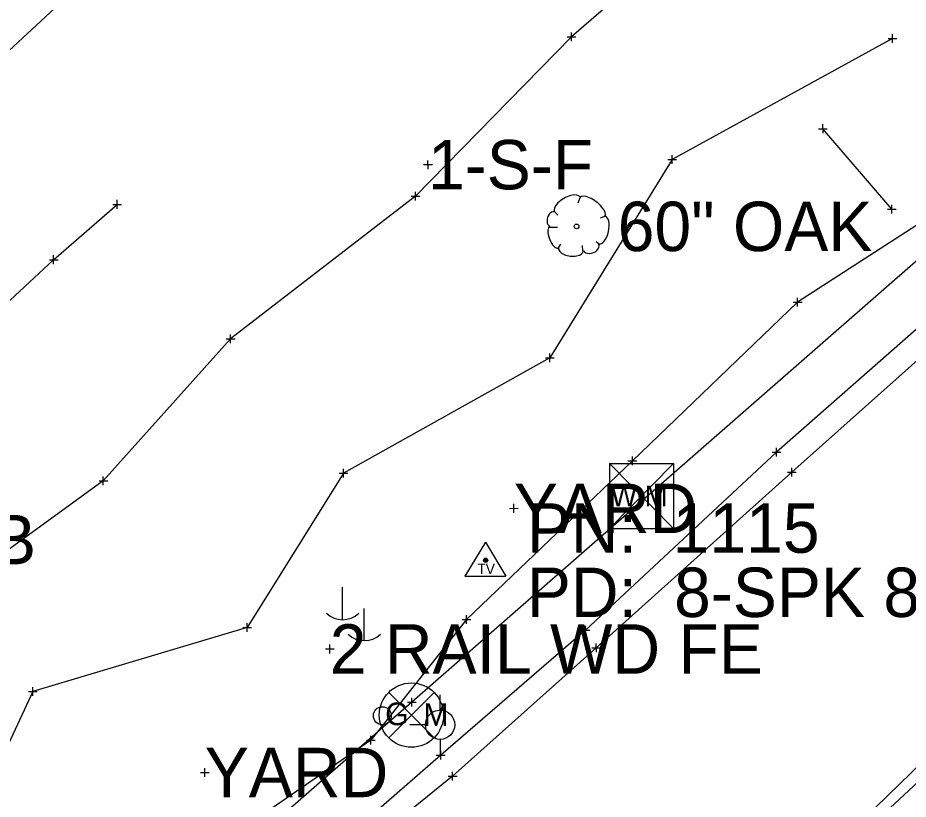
# Model space of a CAD drawing. Extents: x -1 to 1157254, y -1 to 2021979.
# Drawn here: x 1147450.2 to 1147580, y 2017460.4 to 2017574.3 of the extents above; entities that cross this region are included whole.
import ezdxf

# ---------------------------------------------------------------- set-up
doc = ezdxf.new("R2010")
doc.units = 0
for name, color, linetype in [('S_BREAKLINE', 7, 'Continuous'), ('S_BUILDING_ANNOT', 7, 'Continuous'), ('S_CAL_CORNER_ANNOT', 7, 'Continuous'), ('S_CATCH_BASIN', 7, 'Continuous'), ('S_CONTOUR_ANNOT', 7, 'Continuous'), ('S_CTL_TABLE', 7, 'Continuous'), ('S_CURB', 7, 'Continuous'), ('S_DRIVEWAY_ANNOT', 7, 'Continuous'), ('S_DTM_PAVEMENT', 7, 'Continuous'), ('S_EDGE_BITUMINOUS_ANNOT', 7, 'Continuous'), ('S_GAS_UTILITIES_ANNOT', 7, 'Continuous'), ('S_GATE', 7, 'Continuous'), ('S_GATE_ANNOT', 7, 'Continuous')]:
    doc.layers.add(name, color=color, linetype=linetype)

msp = doc.modelspace()

# ---------------------------------------------------------------- linework, layer by layer
at = {"layer": 'S_BREAKLINE'}
for p, q in [((1147518.43, 2017497.83), (1147515.42, 2017492.88)), ((1147518.43, 2017497.83), (1147521.37, 2017492.88)), ((1147515.42, 2017492.88), (1147521.37, 2017492.88))]:
    msp.add_line(p, q, dxfattribs=at)
for radius in [0.311, 0.183, 0.103]:
    msp.add_circle((1147518.43, 2017495.22), radius, dxfattribs=at)
at = {"layer": 'S_BUILDING_ANNOT'}
for p, q in [((1147566.97, 2017558.11), (1147568.24, 2017558.11)), ((1147567.61, 2017557.48), (1147567.6, 2017558.75)), ((1147567.6, 2017558.11), (1147567.6, 2017558.11)), ((1147509.39, 2017552.87), (1147510.66, 2017552.87)), ((1147510.03, 2017552.23), (1147510.02, 2017553.5)), ((1147510.03, 2017552.87), (1147510.03, 2017552.87)), ((1147577, 2017546.39), (1147578.27, 2017546.4)), ((1147577.64, 2017545.76), (1147577.64, 2017547.03)), ((1147577.64, 2017546.4), (1147577.64, 2017546.4)), ((1147560.84, 2017510.32), (1147560.83, 2017511.59)), ((1147560.2, 2017510.95), (1147561.47, 2017510.95)), ((1147560.84, 2017510.95), (1147560.84, 2017510.95)), ((1147563.07, 2017507.42), (1147563.07, 2017508.69)), ((1147562.43, 2017508.05), (1147563.7, 2017508.06)), ((1147563.07, 2017508.05), (1147563.07, 2017508.05)), ((1147522.54, 2017502.14), (1147522.54, 2017503.41)), ((1147521.9, 2017502.77), (1147523.18, 2017502.78)), ((1147522.54, 2017502.77), (1147522.54, 2017502.77)), ((1147533.01, 2017484.38), (1147533.01, 2017485.66)), ((1147532.37, 2017485.02), (1147533.64, 2017485.02)), ((1147533.01, 2017485.02), (1147533.01, 2017485.02)), ((1147495.72, 2017481.64), (1147495.71, 2017482.92)), ((1147534.57, 2017481.82), (1147534.56, 2017483.09)), ((1147495.08, 2017482.28), (1147496.35, 2017482.28)), ((1147495.71, 2017482.28), (1147495.71, 2017482.28)), ((1147533.93, 2017482.45), (1147535.2, 2017482.46)), ((1147534.56, 2017482.45), (1147534.56, 2017482.45)), ((1147507.67, 2017473.88), (1147507.67, 2017475.15)), ((1147507.04, 2017474.52), (1147508.31, 2017474.52)), ((1147507.67, 2017474.52), (1147507.67, 2017474.52)), ((1147511.88, 2017466.17), (1147511.88, 2017467.44)), ((1147511.24, 2017466.8), (1147512.52, 2017466.81)), ((1147511.88, 2017466.81), (1147511.88, 2017466.81)), ((1147477.49, 2017463.64), (1147477.49, 2017464.91)), ((1147476.85, 2017464.27), (1147478.12, 2017464.28)), ((1147477.49, 2017464.27), (1147477.49, 2017464.27)), ((1147512.98, 2017463.73), (1147514.26, 2017463.73)), ((1147513.62, 2017463.09), (1147513.62, 2017464.37)), ((1147513.62, 2017463.73), (1147513.62, 2017463.73))]:
    msp.add_line(p, q, dxfattribs=at)
at = {"layer": 'S_CAL_CORNER_ANNOT'}
for p, q in [((1147504.3, 2017469.33), (1147510.92, 2017475.94)), ((1147504.3, 2017475.94), (1147510.92, 2017469.33))]:
    msp.add_line(p, q, dxfattribs=at)
msp.add_lwpolyline([(1148176.11, 2017926.04), (1148136.14, 2017895.28), (1148103.22, 2017868.95), (1148054.86, 2017832.59), (1147994.13, 2017784.96), (1147955.31, 2017755.81), (1147823.06, 2017654.27), (1147729.59, 2017581.35), (1147643.02, 2017515.61), (1147594.54, 2017475.05), (1147501.21, 2017388.35), (1147435.29, 2017328.79), (1147395.53, 2017293.46), (1147348.75, 2017254.13), (1147258.66, 2017171.57), (1147166.99, 2017089.79), (1147151.24, 2017076.13), (1147027.41, 2016982.56), (1146975.56, 2016939.41), (1146851.18, 2016835.15), (1146821.23, 2016867.05), (1146788.36, 2016903.2)], dxfattribs=at)
msp.add_circle((1147507.61, 2017472.64), 4.68, dxfattribs=at)
at = {"layer": 'S_CATCH_BASIN'}
for p, q in [((1147497.52, 2017491.27), (1147497.52, 2017486.54)), ((1147500.69, 2017488.2), (1147500.69, 2017483.47)), ((1147511.79, 2017473.34), (1147511.79, 2017475.59)), ((1147509.7, 2017471.21), (1147507.37, 2017471.21)), ((1147511.87, 2017466.79), (1147511.87, 2017469.12))]:
    msp.add_line(p, q, dxfattribs=at)
for centre, radius in [((1147503.37, 2017472.55), 1.31), ((1147511.79, 2017471.23), 2.13)]:
    msp.add_circle(centre, radius, dxfattribs=at)
for centre in [(1147497.58, 2017489.96), (1147500.76, 2017486.9)]:
    msp.add_arc(centre, 3.41, 226.3972, 313.6028, dxfattribs=at)
at = {"layer": 'S_CONTOUR_ANNOT'}
for p, q in [((1147536.49, 2017509.31), (1147545.83, 2017509.31)), ((1147536.49, 2017509.31), (1147536.49, 2017499.82)), ((1147536.49, 2017509.31), (1147545.83, 2017499.82)), ((1147545.83, 2017509.31), (1147536.49, 2017499.82)), ((1147545.83, 2017509.31), (1147545.83, 2017499.82)), ((1147536.49, 2017499.82), (1147545.83, 2017499.82))]:
    msp.add_line(p, q, dxfattribs=at)
msp.add_lwpolyline([(1148171.01, 2018007.64), (1148133.82, 2017978.13), (1147884.86, 2017790.18), (1147810.34, 2017733.24), (1147725.21, 2017658.34), (1147638.36, 2017588.8), (1147507.67, 2017474.52), (1147125.41, 2017140.99), (1145970.62, 2016384.06)], dxfattribs=at)
at = {"layer": 'S_CTL_TABLE'}
for p, q in [((1147530.3, 2017571.5), (1147531.57, 2017571.5)), ((1147530.94, 2017570.87), (1147530.93, 2017572.14)), ((1147530.93, 2017571.5), (1147530.93, 2017571.5)), ((1147577.09, 2017571.25), (1147578.36, 2017571.25)), ((1147577.73, 2017570.61), (1147577.73, 2017571.88)), ((1147577.73, 2017571.25), (1147577.73, 2017571.25)), ((1147545.61, 2017552.98), (1147545.61, 2017554.25)), ((1147544.97, 2017553.62), (1147546.24, 2017553.62)), ((1147545.61, 2017553.62), (1147545.61, 2017553.62)), ((1147508.22, 2017547.65), (1147508.22, 2017548.93)), ((1147464.71, 2017546.44), (1147464.7, 2017547.72)), ((1147507.58, 2017548.29), (1147508.85, 2017548.29)), ((1147508.22, 2017548.29), (1147508.22, 2017548.29)), ((1147464.07, 2017547.08), (1147465.34, 2017547.08)), ((1147464.7, 2017547.08), (1147464.7, 2017547.08)), ((1147454.83, 2017539.02), (1147456.1, 2017539.02)), ((1147455.46, 2017538.38), (1147455.46, 2017539.66)), ((1147455.46, 2017539.02), (1147455.46, 2017539.02)), ((1147563.91, 2017532.18), (1147563.91, 2017533.45)), ((1147563.28, 2017532.81), (1147564.55, 2017532.82)), ((1147563.91, 2017532.82), (1147563.91, 2017532.82)), ((1147481.26, 2017526.84), (1147481.26, 2017528.11)), ((1147480.63, 2017527.48), (1147481.9, 2017527.48)), ((1147481.26, 2017527.48), (1147481.26, 2017527.48)), ((1147527.17, 2017524.72), (1147528.44, 2017524.72)), ((1147527.81, 2017524.08), (1147527.8, 2017525.35)), ((1147527.81, 2017524.72), (1147527.81, 2017524.72)), ((1147539.82, 2017509.08), (1147539.82, 2017510.35)), ((1147539.18, 2017509.71), (1147540.46, 2017509.72)), ((1147539.82, 2017509.71), (1147539.82, 2017509.71)), ((1147462.7, 2017506.14), (1147462.7, 2017507.41)), ((1147497.09, 2017507.91), (1147498.36, 2017507.91)), ((1147497.72, 2017507.27), (1147497.72, 2017508.54)), ((1147497.72, 2017507.91), (1147497.72, 2017507.91)), ((1147462.07, 2017506.77), (1147463.34, 2017506.78)), ((1147462.7, 2017506.77), (1147462.7, 2017506.77)), ((1147515, 2017486.56), (1147516.28, 2017486.56)), ((1147515.64, 2017485.92), (1147515.64, 2017487.2)), ((1147515.64, 2017486.56), (1147515.64, 2017486.56)), ((1147483.04, 2017485.4), (1147484.31, 2017485.4)), ((1147483.68, 2017484.76), (1147483.68, 2017486.03)), ((1147483.68, 2017485.4), (1147483.68, 2017485.4)), ((1147452.43, 2017475.46), (1147452.43, 2017476.73)), ((1147451.8, 2017476.09), (1147453.07, 2017476.09)), ((1147452.43, 2017476.09), (1147452.43, 2017476.09)), ((1147501.07, 2017469), (1147502.34, 2017469)), ((1147501.7, 2017468.36), (1147501.7, 2017469.64)), ((1147501.7, 2017469), (1147501.7, 2017469))]:
    msp.add_line(p, q, dxfattribs=at)
at = {"layer": 'S_CURB'}
for p, q in [((1147532.23, 2017548.11), (1147531.85, 2017547.26)), ((1147528.44, 2017546.1), (1147528.94, 2017545.52)), ((1147535.8, 2017545.32), (1147535.14, 2017545.05)), ((1147527.78, 2017543.77), (1147528.9, 2017543.77)), ((1147528.94, 2017540.6), (1147529.41, 2017541.29)), ((1147532.62, 2017540.33), (1147532.54, 2017541.1)), ((1147535.02, 2017541.22), (1147534.56, 2017541.64))]:
    msp.add_line(p, q, dxfattribs=at)
msp.add_circle((1147531.68, 2017543.87), 0.34, dxfattribs=at)
for centre, major_axis, ratio, start_param, end_param in [((1147530.34, 2017547.07), (1.86, 1.08), 0.471018, 0, 3.141593), ((1147533.99, 2017546.74), (-1.81, 1.36), 0.405113, 3.141593, 6.283186), ((1147528.11, 2017544.95), (0.31, 1.03), 0.646762, 0, 3.141593), ((1147535.35, 2017543.34), (0.46, 2.04), 0.482994, 3.141593, 6.283185), ((1147528.41, 2017542.3), (-0.61, 1.6), 0.420543, 6.283185, 9.424777), ((1147533.83, 2017540.82), (1.09, 0.46), 0.711534, 3.141592, 6.283185), ((1147530.87, 2017540.52), (-1.83, 0.19), 0.529943, 0, 3.141593)]:
    msp.add_ellipse(centre, major_axis=major_axis, ratio=ratio, start_param=start_param, end_param=end_param, dxfattribs=at)
at = {"layer": 'S_DRIVEWAY_ANNOT'}
for points in [[(1147744.55, 2017594.5), (1147743.32, 2017593.74), (1147727.5, 2017582.83), (1147686.46, 2017550.47), (1147642.4, 2017515.31), (1147602.36, 2017485.52), (1147573.62, 2017457.57), (1147547.71, 2017425.72), (1147524.37, 2017404.2), (1147507.72, 2017393.36), (1147500.71, 2017387.54)], [(1147606.43, 2017551.94), (1147604.44, 2017550.18), (1147586.8, 2017533.74), (1147560.84, 2017510.95), (1147533.01, 2017485.02), (1147511.88, 2017466.81), (1147499.09, 2017455.65), (1147477.48, 2017437.33), (1147465.18, 2017428.31), (1147462.31, 2017425.15), (1147460.92, 2017422.13), (1147460.83, 2017420.92)], [(1147606.88, 2017551.33), (1147605.4, 2017549.25), (1147589.01, 2017531.2), (1147563.07, 2017508.05), (1147534.56, 2017482.45), (1147513.62, 2017463.73), (1147501.1, 2017453.6), (1147480.7, 2017436.38), (1147469.67, 2017427.46), (1147466.76, 2017424.75), (1147465.52, 2017423.97), (1147462.8, 2017421.19), (1147461.43, 2017420.54)]]:
    msp.add_lwpolyline(points, dxfattribs=at)
at = {"layer": 'S_DTM_PAVEMENT'}
msp.add_lwpolyline([(1147577.64, 2017546.4), (1147567.6, 2017558.11)], dxfattribs=at)
at = {"layer": 'S_EDGE_BITUMINOUS_ANNOT'}
for points in [[(1147523.15, 2017631.06), (1147505.88, 2017620.81), (1147476.34, 2017594.93), (1147446.88, 2017567.62), (1147430.44, 2017551.94), (1147417.22, 2017538.11), (1147382.54, 2017504.51), (1147352.3, 2017476.79)], [(1147558.92, 2017595.76), (1147530.93, 2017571.5), (1147508.22, 2017548.29), (1147481.26, 2017527.48), (1147462.7, 2017506.77), (1147439.97, 2017490.32), (1147411.4, 2017466.84)], [(1147577.73, 2017571.25), (1147545.61, 2017553.62), (1147527.81, 2017524.72), (1147497.72, 2017507.91), (1147483.68, 2017485.4), (1147452.43, 2017476.09), (1147436.29, 2017441.5)], [(1147594.68, 2017552.69), (1147563.91, 2017532.82), (1147539.82, 2017509.71), (1147515.64, 2017486.56), (1147501.7, 2017469), (1147474.21, 2017450.06), (1147451.05, 2017428.59)], [(1147438.42, 2017524.57), (1147445.56, 2017529.88), (1147455.46, 2017539.02), (1147464.7, 2017547.08)]]:
    msp.add_lwpolyline(points, dxfattribs=at)

# ---------------------------------------------------------------- texts
at = {"layer": 'S_BREAKLINE'}
msp.add_text('TV', height=1.499, dxfattribs=at).set_placement((1147517.22, 2017493.21))
at = {"layer": 'S_CAL_CORNER_ANNOT'}
for s, p in [('G', (1147503.79, 2017471.17)), ('M', (1147509.36, 2017471.07))]:
    msp.add_text(s, height=3.3, dxfattribs=at).set_placement(p)
at = {"layer": 'S_CONTOUR_ANNOT'}
msp.add_text('W M', height=2.999, dxfattribs=at).set_placement((1147536.7, 2017503.08))
at = {"layer": 'S_GAS_UTILITIES_ANNOT'}
for s, p in [('PN: ', (1147524.43, 2017496.3)), ('1115', (1147545.69, 2017496.3)), ('PD: ', (1147524.43, 2017486.94)), ('8-SPK 8SPK', (1147545.9, 2017486.94))]:
    msp.add_text(s, height=7.2, dxfattribs=at).set_placement(p)
at = {"layer": 'S_GATE'}
for s, p in [('1-S-F', (1147510.03, 2017549.27)), ('YARD', (1147522.54, 2017499.17)), ('1-S-B', (1147428.29, 2017494.62)), ('2 RAIL WD FE', (1147495.71, 2017478.68)), ('YARD', (1147477.49, 2017460.67))]:
    msp.add_text(s, height=7.2, dxfattribs=at).set_placement(p)
at = {"layer": 'S_GATE_ANNOT'}
msp.add_text('60" OAK', height=7.2, dxfattribs=at).set_placement((1147537.68, 2017540.27))

doc.saveas('drawing.dxf')
